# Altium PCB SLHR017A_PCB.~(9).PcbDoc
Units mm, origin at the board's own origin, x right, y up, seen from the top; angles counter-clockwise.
Board outline 79.38 x 53.34 mm, 2 copper layers (Top Layer, Bottom Layer), stack 1.554 mm thick; 50 components, 16 nets, 75 pads, 30 vias.
Unrouted connection lines stored in the file: 2.
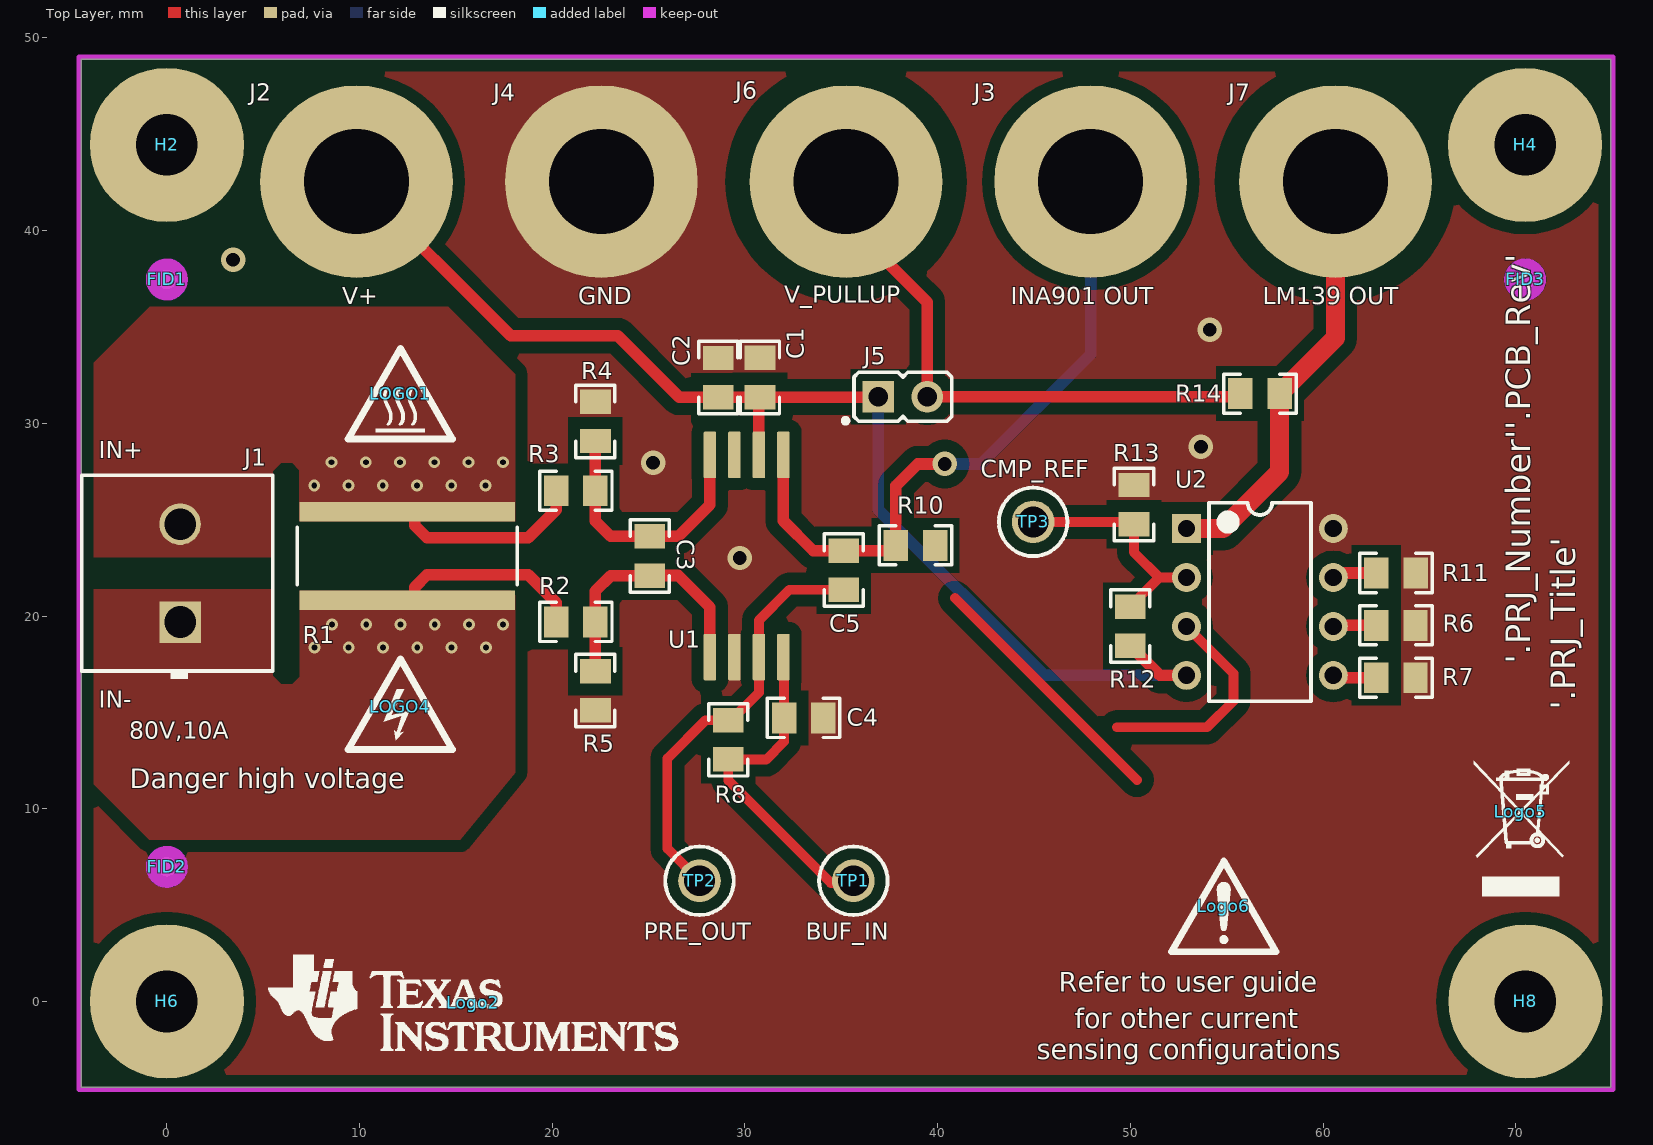
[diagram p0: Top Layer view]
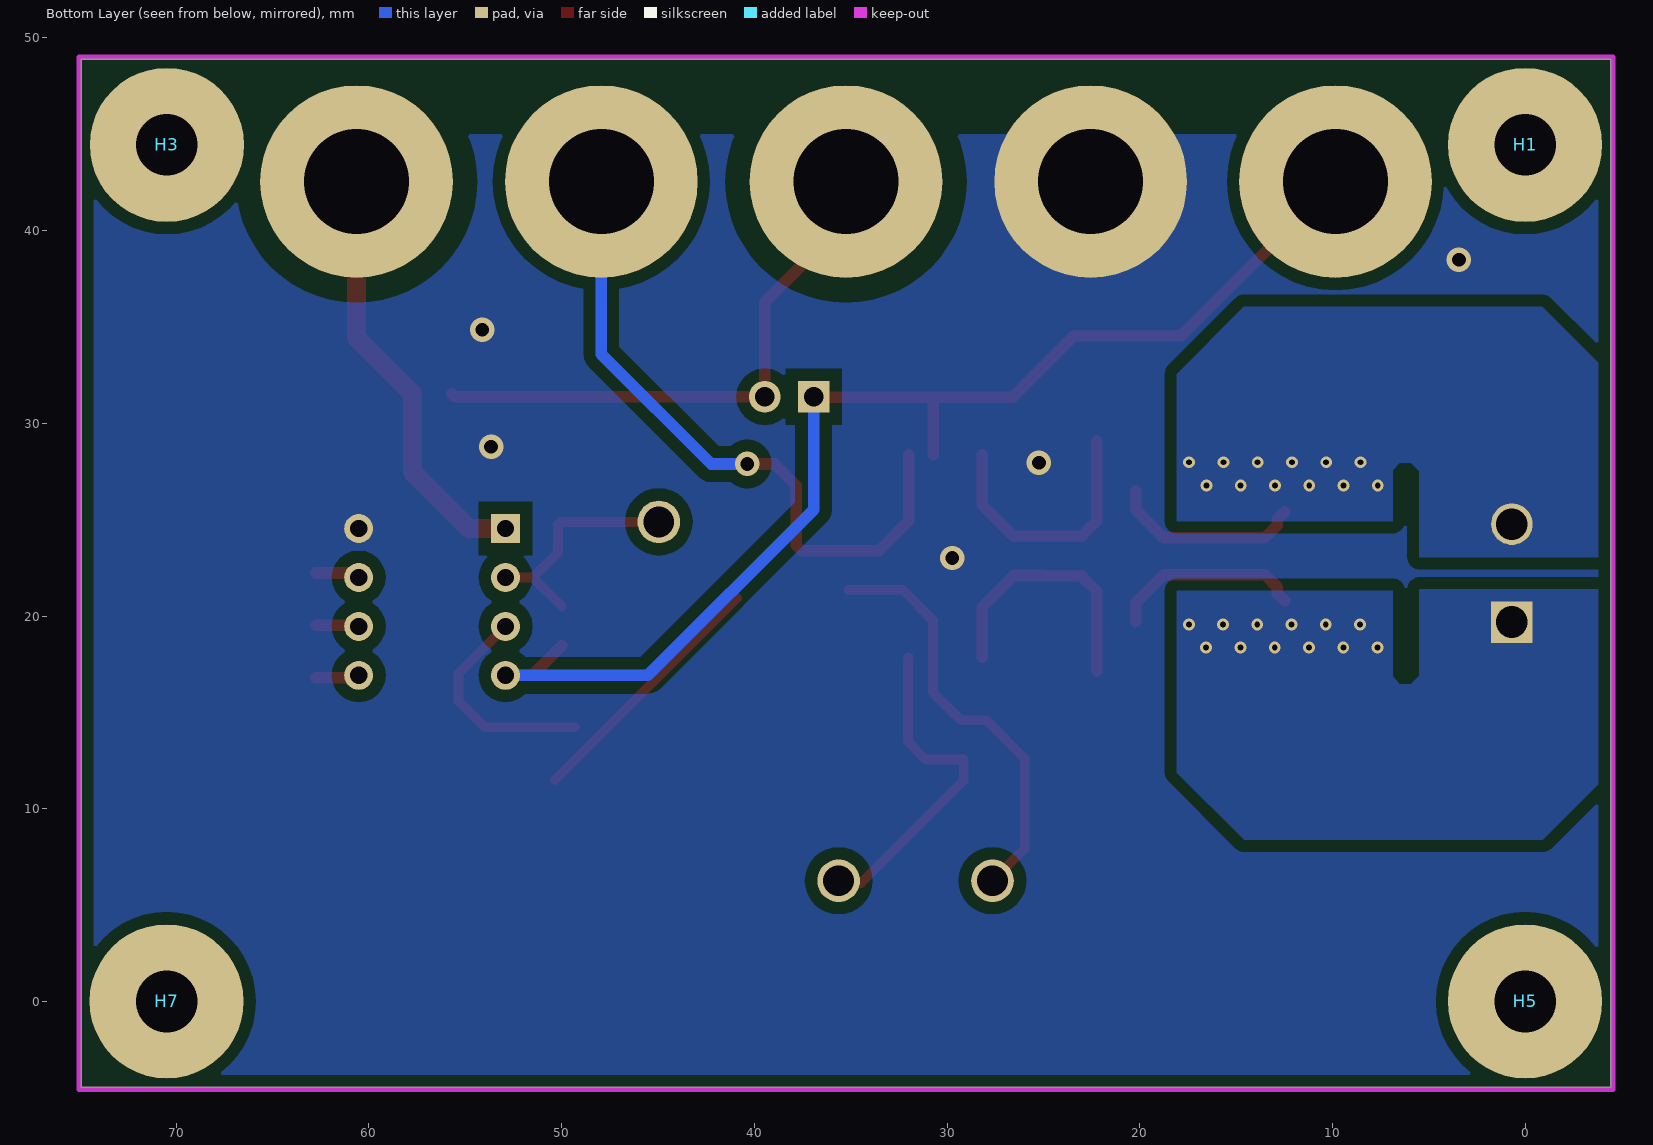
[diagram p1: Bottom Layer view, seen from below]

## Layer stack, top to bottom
Top Solder: solder mask 0.0102, Solder Resist, Dk 3.5
Top Layer: signal copper 0.0533
Dielectric1: core 1.4478, FR-4 High Tg, Dk 4.8
Bottom Layer: signal copper 0.0533
Bottom Solder: solder mask 0.0102, Solder Resist, Dk 3.5

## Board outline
-4.445,-4.445 74.93,-4.445 74.93,48.895 -4.445,48.895
cut-out: -45.497,-56.25 -45.243,-56.25 -45.243,-55.996 -45.497,-55.996

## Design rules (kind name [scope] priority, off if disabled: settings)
AcuteAngle [All] p1: minimum=4.50000000000000E+0001 checktracksonly=FALSE
AssemblyTestPointUsage [All] p1: valid=2
Clearance Clearance_HV [InNetClass('HV_Net')] p1: gap=0.635 ignorepadtopadclearanceinfootprint=TRUE except(1.27: THPad-Poly Poly-Poly)
Clearance Clearance_Keepouts [((IsTrack Or IsArc) And Not InPoly) And IsFree and IsKeepOut vs ((IsTrack Or IsArc) And Not InPoly) And IsFree and IsKeepOut] p2: gap=0 ignorepadtopadclearanceinfootprint=FALSE
Clearance Clearance_Fiducial [InComponentClass('FiducialMark')] p3: gap=0 ignorepadtopadclearanceinfootprint=FALSE
Clearance Clearance_BoardEdge_MountingHoles [OnCopper and InComponentClass('Mounting Holes') vs IsKeepOut] p4: gap=1.016 ignorepadtopadclearanceinfootprint=FALSE except(0.381: Track-THPad)
Clearance Clearance_BoardEdge_Poly [OnCopper and InPoly vs IsKeepOut] p5: gap=0.635 ignorepadtopadclearanceinfootprint=FALSE
Clearance Clearance_Jack_Poly [InPolygon vs InPadClass('Jack')] p6: gap=0.635 ignorepadtopadclearanceinfootprint=FALSE except(1.27: Arc-Poly Track-Poly SMDPad-Poly THPad-Poly Via-Poly Fill-Poly Poly-Poly)
Clearance Clearance_Poly [InPolygon] p7: gap=0.635 ignorepadtopadclearanceinfootprint=FALSE
Clearance [All] p8: gap=0.381 ignorepadtopadclearanceinfootprint=FALSE
ComponentClearance ComponentClearance_MountingHoles_FiducialMarks [InComponentClass('Mounting Holes') vs InComponentClass('FiducialMark')] p1: gap=1.27 collisioncheckmode=3 verticalgap=0.254 showdistances=FALSE
ComponentClearance ComponentClearance_Logo [InComponentClass('Logo')] p2: gap=1.27 collisioncheckmode=3 verticalgap=2540 showdistances=FALSE
ComponentClearance ComponentClearance_ScrewToNut [(HasFootprint('NY PMS 440 0025 PH')) vs (HasFootprint('Keystone_1902C'))] p3: gap=0 collisioncheckmode=3 verticalgap=0 showdistances=FALSE
ComponentClearance ComponentClearance_MountingHoles [InComponentClass('Mounting Holes')] p4: gap=0.762 collisioncheckmode=3 verticalgap=2540 showdistances=FALSE
ComponentClearance [All] p5: gap=0.508 collisioncheckmode=3 verticalgap=0.254 showdistances=FALSE
DiffPairsRouting [All] p1: maxlimit=2.54 minlimit=0.254 mostfreqgap=0.254 toplayer_minwidth=0.381 toplayer_maxwidth=0.381 toplayer_prefwidth=0.381 bottomlayer_minwidth=0.381 bottomlayer_maxwidth=0.381 bottomlayer_prefwidth=0.381 maxuncoupledlength=25.4
FabricationTestPointUsage TestPointUsage [All] p1: valid=2 allowmultiple=FALSE
FabricationTestpoint Testpoint [All] p1: side=3 testpointundercomponent=TRUE minsize=1.016 maxsize=2.54 preferedsize=1.524 minholesize=0 maxholesize=1.016 preferedholesize=0.813 testpointgrid=0.025 allowsidetop=TRUE allowsidebottom=TRUE usegrid=TRUE gridtolerance=0
FanoutControl Fanout_LCC [IsLCC] p1: bgadir=Out bgaviamode=Centered fanoutstyle=Auto fanoutdirection=Alternating viagrid=0.025 // Fanout_LCC (Default Rule)
FanoutControl Fanout_BGA [IsBGA] p2: bgadir=Out bgaviamode=Centered fanoutstyle=Auto fanoutdirection=Alternating viagrid=0.025 // Fanout_BGA (Default Rule)
FanoutControl Fanout_Default [All] p4: bgadir=Out bgaviamode=Centered fanoutstyle=Auto fanoutdirection=Alternating viagrid=0.025 // Fanout_Default (Default Rule)
FanoutControl Fanout_Small [(CompPinCount < 5)] p5: bgadir=Out bgaviamode=Centered fanoutstyle=Auto fanoutdirection=OutThenIn viagrid=0.025 // Fanout_Small (Default Rule)
HoleSize [All] p1: absolutevalues=TRUE maxlimit=6.375 minlimit=0.203 maxpercent=80.000 minpercent=20.000
MinimumAnnularRing [All] p1: minimumring=0.152
MinimumSolderMaskSliver MinimumSolderMaskSliver_Logo [InComponentClass('Logo') vs InComponentClass('Logo')] p1: minsoldermaskwidth=0.018
MinimumSolderMaskSliver [All] p2: minsoldermaskwidth=0.102
PlaneConnect [All] p1: planeconnectstyle=Relief reliefexpansion=0.254 reliefentries=4 reliefconductorwidth=0.254 reliefairgap=0.254
PolygonConnect [All] p1: connectstyle=Direct reliefconductorwidth=0.762 reliefentries=4 polygonreliefangle="90 Angle" airgapwidth=0.381
RoutingVias [All] p1: holewidth=0.305 width=0.61 viastyle="Through Hole" minholewidth=0.305 minwidth=0.61 maxholewidth=0.305 maxwidth=0.61
SilkToBoardRegionClearance [Not ((IsComment or IsDesignator) And (Hide <> 'False')) and not InRegion(1000,500,4000,800)] p1:
SilkToSilkClearance SilkToSilkClearance_Pb-FreeLogo [(HasFootprint('Pb-Free_Overlay_Medium') OR HasFootprint('Pb-Free_Overlay_Small')) vs (HasFootprint('Pb-Free_Overlay_Medium') OR HasFootprint('Pb-Free_Overlay_Small'))] p1: silktosilkclearance=0
SilkToSilkClearance [All] p2: silktosilkclearance=0.102
SilkToSolderMaskClearance SilkToComonentPadClearance [IsPad and InAnycomponent] p1: minsilkscreentomaskgap=0.127 clearancetoexposedcopper=TRUE
SilkToSolderMaskClearance "Silk to Solder Mask Opening" [All] p2: minsilkscreentomaskgap=0.102 clearancetoexposedcopper=FALSE
SolderMaskExpansion [All] p1: expansion=0
Width [All] p1: maxlimit=2.54 minlimit=0.152 preferedwidth=0.254 checkconnectedcopper=TRUE
15 further rules are at their usual default settings.

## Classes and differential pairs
component class Header: J5
component class SLHR017A_MainSheet: C1 C2 C3 C4 C5 J1 J2 J3 J4 J5 J6 J7 R1 R2 R3 R4 R5 R6 R7 R8 R10 R11 R12 R13 R14 TP1 TP2 TP3 U1 U2 U4
component class AssemblyNote: ZZ1 ZZ2 ZZ3
component class FiducialMark: FID1 FID2 FID3
component class SLHR017A_Hardware: FID1 FID2 FID3 H1 H2 H3 H4 H5 H6 H7 H8 LOGO1 Logo2 Logo3 LOGO4 Logo5 Logo6 Logo7 ZZ1 ZZ2 ZZ3
component class Logo: Logo2
component class "Mounting Holes": H2 H4 H6 H8
pad class Jack: J4-1 J6-1 J7-1 J8-1

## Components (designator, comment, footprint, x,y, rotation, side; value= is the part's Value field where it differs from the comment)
C1 "C0805C104K1RACTU" 0805_HV 30.776,32.379 r90 top value=0.1uF
C2 "C0805C103F1GACTU" 0805_HV 28.612,32.375 r90 top value=0.01uF
C3 "C0805C101J1RACTU" 0805_HV 25.062,23.114 r270 top value=100pF
C4 "C0805C103F1GACTU" 0805_HV 33.045,14.714 r0 top value=0.01uF
C5 "C0805C103F1GACTU" 0805_HV 35.127,22.382 r90 top value=0.01uF
FID1 "Fiducial" Fiducial10-20 0,37.465 r270 top locked
FID2 "Fiducial" Fiducial10-20 0,6.985 r0 top locked
FID3 "Fiducial" Fiducial10-20 70.485,37.465 r180 top locked
H1 "1902C" Keystone_1902C 0,44.45 r180 bottom locked
H2 "NY PMS 440 0025 PH" "NY PMS 440 0025 PH" 0,44.45 r0 top locked
H3 "1902C" Keystone_1902C 70.485,44.45 r180 bottom locked
H4 "NY PMS 440 0025 PH" "NY PMS 440 0025 PH" 70.485,44.45 r0 top locked
H5 "1902C" Keystone_1902C 0,0 r180 bottom locked
H6 "NY PMS 440 0025 PH" "NY PMS 440 0025 PH" 0,0 r0 top locked
H7 "1902C" Keystone_1902C 70.498,0 r180 bottom locked
H8 "NY PMS 440 0025 PH" "NY PMS 440 0025 PH" 70.498,0 r0 top locked
J1 "039544-3002" Molex_039544-3002 0.69,22.225 r90 top
J2 "V+" Keystone_575-4 9.842,42.545 r0 top
J3 "INA_OUT" Keystone_575-4 47.942,42.545 r0 top
J4 "GND" Keystone_575-4 22.542,42.545 r0 top
J5 "PBC02SAAN" Sullins_PBC02SAAN 38.191,31.38 r90 top
J6 "VPULLUP" Keystone_575-4 35.242,42.545 r0 top
J7 "COMP_OUT" Keystone_575-4 60.642,42.545 r0 top
LOGO1 "CAUTION HOT SURFACE" IEC_HotSurface_Small 12.115,31.542 r0 top
Logo2 "Texas Instruments" TI_Stacked_Overlay_Small 15.897,-0.073 r0 top
Logo3 "FCC disclaimer" FCC_disclaimer 49.467,-37.52 r270 top locked
LOGO4 "DANGER HIGH VOLTAGE" IEC_HighVoltage_Small 12.116,15.3 r0 top
Logo5 "WEEE logo" WEEE_Minimum 70.251,9.843 r0 top
Logo6 "CAUTION.  READ USER GUIDE BEFORE USE" IEC_Caution_Small 54.848,4.937 r0 top
R1 "KRL11050-C-R050-F-T1" 4320 12.471,23.114 r90 top value=0.05
R2 "ERJ-6GEY0R00V" 0805_HV 21.218,19.693 r0 top value=0
R3 "ERJ-6GEY0R00V" 0805_HV 21.218,26.505 r0 top value=0
R4 "ERJ-6GEY0R00V" 0805_HV 22.234,30.099 r90 top value=0
R5 "ERJ-6GEY0R00V" 0805_HV 22.234,16.129 r90 top value=0
R6 "CRCW080510M0FKEA" 0805_HV 63.782,19.515 r180 top value=10.0Meg
R7 "RNCP0805FTD10K0" 0805_HV 63.782,16.797 r180 top value=10.0k
R8 "ERJ-6GEY0R00V" 0805_HV 29.135,13.577 r90 top value=0
R10 "ERJ-6GEY0R00V" 0805_HV 38.851,23.668 r0 top value=0
R11 "RNCP0805FTD10K0" 0805_HV 63.782,22.233 r0 top value=10.0k
R12 "ERJ-6GEYJ153V" 0805_HV 49.991,19.476 r270 top value=15k
R13 "ERJ-6GEYJ153V" 0805_HV 50.191,25.785 r270 top value=15k
R14 "ERJ-6GEYJ302V" 0805_HV 56.726,31.541 r180 top value=3.0k
TP1 "BUF_IN" Keystone5010 35.624,6.262 r90 top
TP2 "PRE_OUT" Keystone5010 27.64,6.262 r90 top
TP3 "CMP_REF" Keystone5010 44.956,24.887 r90 top
U1 "INA901HKX/EM" HKX0008A_Custom_B 30.088,23.116 r90 top
U2 "LM193AJRLQMLV" NAB0008A 56.722,20.73 r0 top
ZZ1 "These assemblies are ESD sensitive, ESD precautions shall be observed." AssemblyNote 112.471,32.481 r0 top
ZZ2 "These assemblies must be clean and free from flux and all contaminants. Use of no clean flux is not acceptable." AssemblyNote 112.471,30.232 r0 top
ZZ3 "These assemblies must comply with workmanship standards IPC-A-610 Class 2, unless otherwise specified." AssemblyNote 112.471,27.983 r0 top

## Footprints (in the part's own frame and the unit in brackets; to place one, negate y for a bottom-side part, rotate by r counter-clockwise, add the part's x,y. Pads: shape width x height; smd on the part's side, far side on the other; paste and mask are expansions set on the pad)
0805_HV [mil] "0805 with 30mil clearance between pads"
  rect 50x63 smd: 1(-40,0) 2(40,0)
  silkscreen extent -74,-40 74,40, body extent -43,-29 43,29, height 57
4320 [mm] "SUSUMU"
  rect 1x11.2 smd: 1(-2.3,0) 2(2.3,0)
  silkscreen extent -1.5,-5.7 1.5,5.7, body extent -2.6,-5.6 2.6,5.6, height 0.7
AssemblyNote [mm] "Assembly Note"
FCC_disclaimer [mm]
Fiducial10-20 [mm]
  round 1 smd mask+0.5: 1(0,0)
  Top Layer keep-out circle w1.178: c0,0 r0.5
HKX0008A_Custom_B [mm] "CFP, 8-Leads, Body 6.73x6.74mm (max), Pitch 1.27mm, IPC Medium Density"
  rrect15% 2.4x0.65 smd: 1(-5.25,1.905) 2(-5.25,0.635) 3(-5.25,-0.635) 4(-5.25,-1.905) 5(5.25,-1.905) 6(5.25,-0.635) 7(5.25,0.635) 8(5.25,1.905)
  body extent -3.25,-3.24 3.25,3.24, height 2.51
IEC_Caution_Small [mm]
  silkscreen extent -2.72,-2.36 2.72,2.35
IEC_HighVoltage_Small [mm]
  silkscreen extent -2.72,-2.24 2.72,2.47
IEC_HotSurface_Small [mm]
  silkscreen extent -2.72,-2.36 2.72,2.35
Keystone5010 [mil] "Keystone Multipurpose loops"
  round 87 hole 63: 1(0,0)
  silkscreen extent -70,-70 70,70, body extent -63,-63 63,62, height 319
Keystone_575-4 [mm] "Banana Jack"
  round 10 hole 5.45: 1(0,0)
  body extent -3.95,-3.95 3.92,3.93, height 2.36
Keystone_1902C [mil] "Hex Standoff, 4-40 threaded, nylon"
  round 1 on Mech4: 0(0,0)
  body extent -145,-126 146,126, height 501
Molex_039544-3002 [mm] "Terminal Block, 5.08mm, 2x1, TH"
  rect 2.15x2.15 hole 1.65: 1(-2.54,0)
  round 2.15 hole 1.65: 2(2.54,0)
  silkscreen extent -5.5,-4.8 5.08,5.11, body extent -5.08,-4.8 5.08,5.11, height 14.48
NAB0008A [mm] "DIP, 8-Leads, Row Spacing 7.62mm, Pitch 2.54mm, Body 9.78x6.73mm"
  rect 1.5x1.5 hole 0.9: 1(-3.81,3.81)
  round 1.5 hole 0.9: 2(-3.81,1.27) 3(-3.81,-1.27) 4(-3.81,-3.81) 5(3.81,-3.81) 6(3.81,-1.27) 7(3.81,1.27) 8(3.81,3.81)
  silkscreen extent -2.65,-5.15 2.65,5.15, body extent -3.91,-5.08 3.96,5.08, height 5.17
"NY PMS 440 0025 PH" [mm] "4-40 nylon screw and mounting hole"
  round 8 hole 3.2: 1(0,0)
  body extent -3.3,-3.3 3.3,3.3, height 2.69
Sullins_PBC02SAAN [mm] "Sullins 100mil, 1x2, 230 mil above insulator"
  rect 1.65x1.65 hole 1.016: 1(0,1.27)
  round 1.65 hole 1.016: 2(0,-1.27)
  silkscreen extent -1.37,-2.54 1.27,3.1, body extent -1.27,-2.54 1.27,2.54, height 8.38
TI_Stacked_Overlay_Small [mm]
  silkscreen extent -10.63,-2.49 10.63,2.49
WEEE_Minimum [mm] "WEEElie bin"
  silkscreen extent -2.42,-4.38 2.52,2.65

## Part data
C1: library part CMP-0007722-2, "CAP, CERM, 0.1 uF, 100 V, +/- 10%, X7R, 0805", Cap_Case=0805, Manufacturer=Kemet, Supplier Part Number 1=399-3486-1-ND, TempCo=X7R, Tolerance_%=10%, Value1="0.064 ohm", Value2=100V, ValueDisplayed=0.1uF
C2 C4 C5: library part CMP-0007716-2, "CAP, CERM, 0.01 uF, 100 V, +/- 1%, C0G/NP0, 0805", Cap_Case=0805, Manufacturer=Kemet, Supplier Part Number 1=399-11160-1-ND, TempCo=C0G/NP0, Tolerance_%=1%, Value1=Unknown, Value2=100V, ValueDisplayed=0.01uF
C3: library part CMP-0007706-2, "CAP, CERM, 100 pF, 100 V, +/- 5%, X7R, 0805", Cap_Case=0805, Manufacturer=Kemet, Supplier Part Number 1=80-C0805C101J1R, TempCo=X7R, Tolerance_%=5%, Value1=Unknown, Value2=100V, ValueDisplayed=100pF
FID1 FID2 FID3: library part CMP-0077181-1, "Fiducial mark.  There is nothing to buy or mount.", Manufacturer=N/A
H1 H3 H5 H7: library part CMP-0003610-1, "Standoff, Hex, 0.5\"L #4-40 Nylon", Manufacturer=Keystone, Supplier Part Number 1=36-1902C-ND
H2 H4 H6 H8: library part CMP-0003617-1, "Machine Screw, Round, #4-40 x 1/4, Nylon, Philips panhead", Manufacturer="B&F Fastener Supply", Supplier Part Number 1=H542-ND
J1: library part CMP-0055345-1, "Terminal Block, 5.08mm, 2x1, TH", Color=Black, Current_A=15A, Manufacturer=Molex, Supplier Part Number 1=WM7853-ND, Voltage_V=300V
J2 J3 J4 J6 J7: library part CMP-0055165-2, "Standard Banana Jack, Uninsulated, 5.5mm", Manufacturer=Keystone, PartNumber=575-4, Supplier Part Number 1=36-575-4-ND
J5: library part CMP-0054566-1, "Header, 100mil, 2x1, Gold, TH", Color=Black, Current_A=3A, Manufacturer="Sullins Connector Solutions", Supplier Part Number 1=S1011E-02-ND, Voltage_V=1.8kV
LOGO1: library part CMP-0074837-1, "IEC 61010-1 Hot Surface Warning"
Logo2: library part CMP-0074838-1, "Texas Instrument Corporate Signature"
Logo3: library part CMP-0074847-1, "FCC_disclaimer"
LOGO4: library part CMP-0074835-1, "IEC 61010-1 High Voltage Warning"
Logo5: library part CMP-0074769-1
Logo6: library part CMP-0074836-1, "IEC 61010-1 Caution Warning"
R1: library part CMP-0015099-2, "RES, 0.05, 1%, 6 W, 4320_WIDE", Manufacturer="Susumu Co Ltd", Power_W=6W, Supplier Part Number 1=KRL11C.050CT-ND, TempCo="50 ppm/C", Tolerance_%=1%, Value_Code=R050, ValueDisplayed=0.05
R2 R3 R4 R5 R8 R10: library part CMP-0020616-3, "RES, 0, 5%, 0.125 W, AEC-Q200 Grade 0, 0805", Manufacturer=Panasonic, Power_W=125mW, Supplier Part Number 1=P0.0ACT-ND, TempCo="600 ppm/C", Tolerance_%=5%, Value2=0.125W, Value_Code=0000, ValueDisplayed=0
R6: library part CMP-0020846-3, "RES, 10.0 M, 1%, 0.125 W, AEC-Q200 Grade 0, 0805", Manufacturer=Vishay-Dale, Power_W=125mW, Supplier Part Number 1=541-10.0MCCT-ND, TempCo="100 ppm/C", Tolerance_%=1%, Value2=0.125W, Value_Code=10M0, ValueDisplayed=10.0M
R7 R11: library part CMP-0084247-1, "RES, 10.0 k, 1%, 0.25 W, AEC-Q200 Grade 0, 0805", Manufacturer="Stackpole Electronics Inc", Power_W=250mW, TempCo="100 ppm/C", Tolerance_%=1%, Value2=0.25W, Value_Code=10k0, ValueDisplayed=10.0k
R12 R13: library part CMP-0020646-3, "RES, 15 k, 5%, 0.125 W, AEC-Q200 Grade 0, 0805", Manufacturer=Panasonic, Power_W=125mW, Supplier Part Number 1=P15KACT-ND, TempCo="200 ppm/C", Tolerance_%=5%, Value2=0.125W, Value_Code=15k0, ValueDisplayed=15k
R14: library part CMP-0020698-3, "RES, 3.0 k, 5%, 0.125 W, AEC-Q200 Grade 0, 0805", Manufacturer=Panasonic, Power_W=125mW, Supplier Part Number 1=P3.0KACT-ND, TempCo="200 ppm/C", Tolerance_%=5%, Value2=0.125W, Value_Code=3k00, ValueDisplayed=3.0k
TP1 TP2 TP3: library part CMP-0055147-1, "Test Point, Multipurpose, Red, TH", Color=Red, Manufacturer=Keystone, PartNumber=5010, Supplier Part Number 1=36-5010-ND
U1: library part CMP-0081563-2, "Voltage Output, Unidirectional Measurement Current-Shunt Monitor, HKX0008A (CFP-8)", Alternate Manufacturer="Texas Instruments", Rating=Space
U2: library part CMP-0067897-1, "Low Power Low Offset Voltage Dual Comparator, 8-pin CerDIP", Manufacturer="Texas Instruments", Package Reference=NAB0008A, PackageTopMarking="NSZSSXXYYA*LM193AJRLV Q*5962R*9452603VPA", PowerWise=N
ZZ1: library part CMP-0077236-1
ZZ2: library part CMP-0077237-1
ZZ3: library part CMP-0077238-1

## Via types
v1: diameter 0.61, hole 0.305, Top Layer to Bottom Layer, tented both sides, 24 vias
v2: diameter 1.27, hole 0.711, Top Layer to Bottom Layer, 6 vias

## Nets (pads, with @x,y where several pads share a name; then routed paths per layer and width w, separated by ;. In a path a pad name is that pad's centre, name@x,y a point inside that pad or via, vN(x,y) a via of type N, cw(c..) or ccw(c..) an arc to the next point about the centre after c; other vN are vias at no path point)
GND: C1.2 C2.2 C4.2 J4.1 R4.2 R5.1 R6.1 R7.1 R11.2 R13.1 U1.2 U2.8
  other v2: 29.733,23.012 25.228,27.961 53.663,28.785 54.117,34.857 3.433,38.489
NetC3_1: C3.1 R3.2 R4.1 U1.8 | length 13.7
  Top Layer w0.6: R4.1 R3.2 22.234,24.933 23.037,24.13 C3.1 26.542,24.13 28.183,25.77 U1.8
NetC3_2: C3.2 R2.2 R5.2 U1.1 | length 13.7
  Top Layer w0.6: R5.2 R2.2 22.234,21.295 23.037,22.098 C3.2 ; C3.2@25.062,22.102 26.542,22.102 28.183,20.462 U1.1
NetC4_1: C4.1 R8.1 TP1.1 U1.4 | length 17.5
  Top Layer w0.508: U1.4 32.029,17.83 C4.1 32.029,13.484 31.106,12.561 R8.1 29.135,11.47 34.456,6.149 TP1.1@35.624,6.149
NetC5_1: C5.1 R8.2 TP2.1 U1.3 | length 22
  Top Layer w0.508: TP2.1 25.97,7.932 25.97,12.608 27.956,14.593 R8.2 29.279,14.593 30.723,16.037 U1.3 30.723,19.783 32.306,21.366 C5.1
NetC5_2: C5.2 J3.1 R10.1 U1.5 | length 35
  Top Layer w0.6: U1.5 31.993,24.938 33.533,23.398 C5.2 37.565,23.398 R10.1 37.835,26.76 38.967,27.891 v2(40.371,27.891)
  Bottom Layer w0.6: v2(40.371,27.891) 42.24,27.891 47.942,33.594 J3.1
NetJ1_1: J1.1 R1.1 R2.1 | length 10.1
  Top Layer w0.6: R1.1@12.471,20.785 12.86,21.174 12.86,21.501 13.499,22.14 18.745,22.14 20.202,20.682 R2.1
  other v1: 7.655,18.364 9.433,18.364 11.211,18.364 12.989,18.364 14.767,18.364 16.557,18.364 8.565,19.558 10.343,19.558 12.121,19.558 13.899,19.558 15.671,19.558 17.444,19.558
NetJ1_2: J1.2 R1.2 R3.1 | length 10.1
  Top Layer w0.6: R1.2 12.86,25.025 12.86,24.698 13.499,24.059 18.745,24.059 20.202,25.516 R3.1
  other v1: 7.648,26.775 9.426,26.775 11.204,26.775 12.982,26.775 14.76,26.775 16.538,26.775 8.546,27.983 10.324,27.983 12.102,27.983 13.88,27.983 15.658,27.983 17.436,27.983
NetJ5_2: J5.2 J6.1 R14.2 | length 29.2
  Top Layer w0.6: J6.1 35.242,40.506 39.461,36.287 J5.2 55.549,31.38 R14.2
NetJ7_1: J7.1 R14.1 U2.1 | length 22.3
  Top Layer w1: U2.1 54.802,24.54 57.742,27.48 R14.1 60.642,34.441 J7.1
NetR6_2: R6.2 U2.6 | length 2.3
  Top Layer w0.6: U2.6 60.587,19.515 R6.2
NetR7_2: R7.2 U2.5 | length 2.3
  Top Layer w0.6: U2.5 60.656,16.797 R7.2
NetR10_2: R10.2 U2.3 | length 24.8
  Top Layer w0.508: 40.905,20.935 50.345,11.496 ; 49.307,14.229 53.98,14.229 55.349,15.598 55.349,17.024 U2.3
NetR11_1: R11.1 U2.7 | length 2.3
  Top Layer w0.6: U2.7 60.765,22.233 R11.1
NetR12_1: R12.1 R13.2 TP3.1 U2.2 | length 12.1
  Top Layer w0.508: TP3.1 50.072,24.887 R13.2 50.191,23.308 51.499,22 ; R12.1 51.499,22 ; U2.2 51.499,22
V+: C1.1 C2.1 J2.1 J5.1 R12.2 U1.6 U2.4 | length 63.7
  Top Layer w0.6: J2.1 17.843,34.544 23.399,34.544 26.584,31.359 C2.1 28.617,31.363 C1.1 ; U1.6 30.723,31.31 C1.1 ; J5.1@36.887,31.552 36.699,31.363 C1.1 ; R12.2 51.531,16.92 U2.4
  Bottom Layer w0.6: J5.1 36.921,25.522 45.523,16.92 U2.4
pads on no net: FID1.1 FID2.1 FID3.1 H1.0 H2.1 H3.0 H4.1 H5.0 H6.1 H7.0 H8.1 U1.7

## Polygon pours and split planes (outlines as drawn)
NetJ1_1 on Bottom Layer "NETJ1_1_L02_P278" (solid, remove dead copper, pour order 278): 18.071,21.311 18.071,11.876 14.686,8.49 14.585,8.383 -0.914,8.383 -4.406,11.876 -4.406,21.383 5.469,21.383 5.49,21.404 5.49,16.907 5.934,16.463 6.505,16.463 6.861,16.865 6.861,21.311
NetJ1_2 on Bottom Layer "NETJ1_2_L02_P280" (solid, remove dead copper, pour order 280): 18.071,24.914 18.082,32.554 14.697,35.939 14.596,36.046 -0.903,36.046 -4.395,32.554 -4.395,23.046 5.48,23.046 5.501,23.025 5.501,27.522 5.944,27.966 6.516,27.966 6.872,27.565 6.872,24.918
GND on Bottom Layer "GND" (solid, remove dead copper, pour order 282): -4.761,-8.326 74.61,-8.326 74.61,45.014 74.61,45.015 -4.76,45.015 -4.763,45.012
NetJ1_2 on Top Layer "NETJ1_2_L01_P272" (solid, remove dead copper, pour order 272): 18.071,24.914 18.082,32.554 14.697,35.939 14.596,36.046 -0.903,36.046 -4.395,32.554 -4.395,23.046 5.48,23.046 5.501,23.025 5.501,27.522 5.944,27.966 6.516,27.966 6.872,27.565 6.872,24.918
no net on Top Layer "NONET_L01_P288" (solid, remove dead copper, pour order 288): 18.076,11.338
NetJ1_1 on Top Layer "NETJ1_1_L01_P274" (solid, remove dead copper, pour order 274): 18.071,21.286 18.087,21.27 18.071,11.876 15.188,8.342 15.147,8.383 -0.914,8.383 -4.406,11.876 -4.406,21.383 5.469,21.383 5.49,21.404 5.49,16.907 5.934,16.463 6.505,16.463 6.898,16.856 6.898,21.311 18.024,21.311 18.035,21.299
GND on Top Layer "GND_L01_P286" (solid, remove dead copper, pour order 286): -4.556,49.057 -4.554,49.055 74.816,49.055 74.816,-4.285 -4.559,-4.285

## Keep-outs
Keep-Out Layer:
  lines w0.254: -4.572,-4.572 75.057,-4.572 75.057,49.022 -4.572,49.022 -4.572,-4.572
  text ".Layer_Name" at -13.265,-39.092 h1.52

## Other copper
Top Layer:
  text ".Layer_Name" at -13.265,-39.092 h1.52
Bottom Layer:
  text ".Layer_Name" at -13.265,-39.092 h1.52

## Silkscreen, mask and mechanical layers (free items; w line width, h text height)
Top Overlay:
  text "V_PULLUP" at 32.038,36.262 h0.89
  text "V+" at 9.102,36.188 h0.89
  text "GND" at 21.358,36.188 h0.89
  text "INA901 OUT" at 43.795,36.188 h0.89
  text "LM139 OUT" at 56.865,36.188 h0.89
  text "IN+" at -3.549,28.193 h0.89
  text "'.PRJ_Number''.PCB_Rev'" at 70.744,17.524 h1.27 r90
  text "IN-" at -3.549,15.24 h0.89
  text "'.PRJ_Title'" at 73.087,15.128 h1.27 r90
  text "80V,10A" at -1.956,13.639 h0.89
  text "Danger high voltage" at -1.922,11.062 h1.02
  text "Refer to user guide" at 46.292,0.496 h1.02
  text "for other current" at 47.105,-1.396 h1.02
  text "sensing configurations" at 45.131,-3.007 h1.02
  text ".Layer_Name" at -13.265,-39.092 h1.52
Bottom Overlay:
  text ".Layer_Name" at -13.265,-39.092 h1.52
Top Paste:
  text ".Layer_Name" at -13.265,-39.092 h1.52
Bottom Paste:
  text ".Layer_Name" at -13.265,-39.092 h1.52
Top Solder:
  text ".Layer_Name" at -13.265,-39.092 h1.52
  text ".Layer_Name" at -13.265,-39.092 h1.52
Bottom Solder:
  text ".Layer_Name" at -13.265,-39.092 h1.52
Drill Guide:
  text ".Layer_Name" at -13.265,-39.092 h1.52
M1 Board Outline:
  the board outline again, w0.254
  text ".Layer_Name" at -13.265,-39.092 h1.52
M2 Board Dimensions:
  rectangle: -24.745,-27.446 -15.22,-24.271
  rectangle: -27.92,-24.271 -24.745,-21.096
  lines w0.178: -27.92,-24.271 -2.52,-24.271 ; -24.745,-27.446 -24.745,-21.096 ; -21.57,-27.446 -21.57,-21.096 ; -15.22,-27.446 -15.22,-21.096 ; -8.87,-27.446 -8.87,-21.096 ; -27.92,-27.446 -27.92,-21.096 -2.52,-21.096 -2.52,-27.446 -27.92,-27.446
  text ".Layer_Name" at -13.265,-39.092 h1.52
M3 3D STEP Top:
  text ".Layer_Name" at -13.265,-39.092 h1.52
M4 3D STEP Bottom:
  text ".Layer_Name" at -13.265,-39.092 h1.52
M5 Assembly Top:
  lines w0.254: -35.337,-40.913 132.303,-40.913 ; -35.337,-35.748 132.354,-35.748 ; -35.337,-30.583 -35.337,-46.077 66.39,-46.077 132.354,-46.077 132.354,-30.583 -35.325,-30.583 -35.325,-46.077 4.693,-46.077 ; 27.274,-46.077 27.274,-30.583 ; 59.456,-35.748 59.456,-30.583 ; 80.792,-35.748 80.792,-30.583 ; 96.59,-46.242 96.59,-41.09
  text "COMPONENTS MARKED 'DNP' SHOULD NOT BE POPULATED." at 1.378,-25.376 h1.52
  text "ASSEMBLY VARIANT:" at 1.366,-28.31 h1.52
  text ".VariantName" at 27.68,-28.31 h1.52
  text "PCB VIEWED FROM TOP SIDE" at -33.724,-33.94 h1.52
  text "BOARD #:" at 29.179,-33.94 h1.52
  text ".PRJ_Number" at 43.034,-33.94 h1.52
  text "REV:" at 64.485,-33.94 h1.52
  text ".PCB_Rev" at 71.889,-33.94 h1.52
  text "SVN REV:" at 85.77,-33.94 h1.52
  text ".VersionControl_RevNumber" at 98.622,-33.94 h1.52
  text "TID #:" at 29.179,-39.105 h1.52
  text ".TID" at 43.034,-39.105 h1.52
  text "PLOT NAME =" at -33.724,-44.32 h1.52
  text ".plot_File_Name" at -13.265,-44.32 h1.52
  text "GENERATED    :" at 29.23,-44.32 h1.52
  text ".Print_Date" at 51.315,-44.32 h1.52
  text ".Print_Time" at 69.831,-44.32 h1.52
  text "TEXAS INSTRUMENTS" at 101.95,-44.32 h1.52
M6 Assembly Bottom:
  lines w0.254: -35.35,-35.761 132.341,-35.761 ; -35.299,-40.925 132.341,-40.925 ; 0.413,-46.255 0.413,-41.103 ; 16.212,-35.761 16.212,-30.596 ; 37.548,-35.761 37.548,-30.596 ; 69.73,-46.09 69.73,-30.596 ; 92.31,-46.09 132.328,-46.09 132.328,-30.596 -35.35,-30.596 -35.35,-46.09 30.614,-46.09 132.341,-46.09 132.341,-30.596
  text "COMPONENTS MARKED 'DNP' SHOULD NOT BE POPULATED." at 127.07,-25.363 h1.52
  text ".VariantName" at 100.553,-28.31 h1.52
  text "ASSEMBLY VARIANT:" at 126.943,-28.31 h1.52
  text ".VersionControl_RevNumber" at -1.619,-33.953 h1.52
  text "SVN REV:" at 11.234,-33.953 h1.52
  text ".PCB_Rev" at 25.115,-33.953 h1.52
  text "REV:" at 32.519,-33.953 h1.52
  text ".PRJ_Number" at 53.969,-33.953 h1.52
  text "BOARD #:" at 67.825,-33.953 h1.52
  text "PCB VIEWED FROM BOTTOM SIDE" at 130.728,-33.953 h1.52
  text ".TID" at 53.969,-39.118 h1.52
  text "TID #:" at 67.825,-39.118 h1.52
  text "TEXAS INSTRUMENTS" at -4.946,-44.333 h1.52
  text ".Print_Time" at 27.172,-44.333 h1.52
  text ".Print_Date" at 45.689,-44.333 h1.52
  text "GENERATED    :" at 67.774,-44.333 h1.52
  text ".plot_File_Name" at 110.268,-44.333 h1.52
  text "PLOT NAME =" at 130.728,-44.333 h1.52
M7 LPKF Text Top:
  text ".Layer_Name" at -13.265,-39.092 h1.52
M8 LPKF Text Bottom:
  text ".Layer_Name" at -13.265,-39.092 h1.52
M9 Title Sheet:
  drawing of 57 lines, arcs and shapes, not listed
  text "1" at -9.129,186.841 h1.78
  text "2" at 54.261,186.841 h1.78
  text "3" at 117.491,186.841 h1.78
  text "4" at 181.16,186.841 h1.78
  text "5" at 244.634,186.841 h1.78
  text "6" at 308.261,186.841 h1.78
  text "A" at -38.5,157.809 h1.78
  text "A" at 337.42,157.809 h1.78
  text "B" at -38.5,97.357 h1.78
  text "B" at 337.42,97.357 h1.78
  text "C" at -38.5,37.032 h1.78
  text "C" at 337.42,37.032 h1.78
  text "PROJECT TITLE:" at 260.204,-10.238 h1.14
  text ".PRJ_Title" at 261.474,-13.624 h1.78
  text "DESIGNED FOR:" at 260.204,-17.883 h1.14
  text ".PRJ_Customer" at 261.474,-21.439 h1.78
  text "D" at -38.5,-23.166 h1.78
  text "D" at 337.42,-23.166 h1.78
  text "FILE NAME:" at 260.204,-25.503 h1.14
  text ".PCB_File_Name_No_Path" at 261.474,-28.551 h1.78
  text "Texas Instruments (TI) and/or its licensors do not warrant the accuracy or completeness of this specification" at 133.979,-32.662 h1.14
  text "ENGINEER:" at 260.204,-32.869 h1.14
  text "LAYOUT BY:" at 298.431,-32.869 h1.14
  text "or any information contained therein. TI and/or its licensors do not warrant that this design will meet" at 132.837,-35.524 h1.14
  text ".PRJ_Engineer" at 261.474,-36.806 h1.78
  text ".PCB_Layout" at 299.714,-36.806 h1.78
  text "the specifications, will be suitable for your application or fit for any particular purpose, or will operate in" at 132.837,-38.385 h1.14
  text ".Layer_Name" at -13.265,-39.092 h1.52
  text "ALTIUM DESIGNER VERSION:" at 298.431,-40.743 h1.14
  text "an implementation. TI and/or its licensors do not warrant that the design is production worthy. You should" at 132.837,-41.247 h1.14
  text "completely validate and test your design implementation to confirm the system functionality for your application." at 133.979,-44.109 h1.14
  text ".print_Scale" at 261.474,-44.13 h1.78
  text ".Application_BuildNumber" at 299.714,-44.13 h1.78
  text "1" at -9.129,-49.379 h1.78
  text "2" at 54.261,-49.379 h1.78
  text "3" at 117.491,-49.379 h1.78
  text "4" at 181.16,-49.379 h1.78
  text "5" at 244.634,-49.379 h1.78
  text "6" at 291.82,-49.527 h1.78
  text "WO#307451-7449-D" at 301.978,-49.59 h1.78
M10 Fab Notes:
  drawing of 189 lines, arcs and shapes, not listed
  text "DESIGN INFORMATION" at 286.926,144.161 h1.52
  text "20" at 297.351,140.825 h1.52
  text "MIN. TRACK WIDTH:" at 270.554,140.805 h1.52
  text "MIL" at 302.329,140.805 h1.52
  text "MIN. CLEARANCE:" at 270.554,137.652 h1.52
  text "MIL" at 302.329,137.652 h1.52
  text "19.7" at 296.193,137.59 h1.52
  text "24" at 296.867,134.714 h1.52
  text "MIN. VIA PAD SIZE:" at 270.554,134.499 h1.52
  text "MIL" at 302.329,134.499 h1.52
  text "0.05mm (2MIL)" at 288.207,131.199 h1.52
  text "MINIMUM ANNULAR RING" at 262.191,130.991 h1.52
  text "EXTERNAL" at 306.19,130.991 h1.52
  text "PER" at 267.271,128.193 h1.52
  text "IPC-D-275 CLASS 2 LEVEL C" at 272.859,128.193 h1.52
  text "MIL, HOLES" at 310.661,125.641 h1.52
  text "+/-" at 300.692,125.423 h1.52
  text "+/-" at 322.384,125.423 h1.52
  text "REGISTRATION TOLERANCES:" at 262.191,125.396 h1.52
  text "METAL" at 292.666,125.396 h1.52
  text "5" at 307.301,125.396 h1.52
  text "3" at 328.459,125.396 h1.52
  text "MIL" at 331.412,125.396 h1.52
  text "HOLE SIZE TOLERANCE (UNLESS OTHERWISE SPECIFIED):" at 262.191,122.899 h1.52
  text "+/-" at 322.384,122.826 h1.52
  text "3" at 328.459,122.799 h1.52
  text "MIL" at 331.412,122.799 h1.52
  text "MATERIAL:" at 260.292,119.303 h1.52
  text "FR-4 High Tg" at 285.348,116.038 h1.52
  text "FR-408" at 270.986,115.721 h1.52
  text "OTHER" at 308.781,115.721 h1.52
  text "X" at 281.581,115.683 h1.52
  text "62 MIL (1.6mm) +/-10%" at 279.116,112.088 h1.52
  text "X" at 276.066,112.025 h1.52
  text "THICKNESS:" at 262.191,111.879 h1.52
  text "OTHER" at 311.753,111.879 h1.52
  text "TOLERANCE:" at 262.191,108.366 h1.52
  text "X" at 283.737,108.366 h1.52
  text "ANSI IPC-6012 TYPE 3 CLASS 2" at 288.258,108.366 h1.52
  text "OTHER +/-" at 288.258,104.703 h1.52
  text "BOW & TWIST:" at 262.191,101.015 h1.52
  text "X" at 283.737,101.015 h1.52
  text "ANSI IPC-6012 TYPE 3 CLASS 2" at 288.258,101.015 h1.52
  text "OTHER +/-" at 288.258,97.289 h1.52
  text "DRILLING:" at 260.292,93.972 h1.52
  text "NC_DRILL FILES" at 305.022,91.3 h1.52
  text "REFERENCE:" at 262.191,91.2 h1.52
  text "X" at 278.885,91.197 h1.52
  text "AS SHOWN" at 283.406,91.2 h1.52
  text "X" at 301.771,91.2 h1.52
  text "OTHER" at 312.591,87.587 h1.52
  text "PTH COPPER THICKNESS:" at 262.183,87.497 h1.52
  text "X" at 291.12,87.497 h1.52
  text "20-30 um" at 294.371,87.497 h1.52
  text "BOARD FINISH:" at 260.292,83.748 h1.52
  text "SILKSCREEN:" at 264.235,80.951 h1.52
  text "X" at 288.563,80.951 h1.52
  text "TOP" at 291.534,80.951 h1.52
  text "BOTTOM" at 304.514,80.951 h1.52
  text "SILKSCREEN COLOR:" at 264.235,77.009 h1.52
  text "X" at 288.537,77.009 h1.52
  text "WHITE" at 291.534,77.009 h1.52
  text "OTHER" at 304.514,77.009 h1.52
  text "X" at 291.777,73.465 h1.52
  text "GREEN" at 294.862,73.365 h1.52
  text "OTHER" at 310.559,73.365 h1.52
  text "SOLDER RESIST COLOR:" at 264.235,73.191 h1.52
  text "X" at 291.865,69.447 h1.52
  text "MATTE" at 294.862,69.447 h1.52
  text "SEMI-GLOSS" at 310.547,69.431 h1.52
  text "IMMERSION GOLD (ENIG)" at 287.242,65.059 h1.52
  text "ENEPIG" at 321.215,64.876 h1.52
  text "SURFACE FINISH:" at 260.292,64.85 h1.52
  text "X" at 282.721,64.85 h1.52
  text "IMM. TIN/SILVER OR EQUIV" at 268.663,61.362 h1.52
  text "OTHER" at 305.022,61.262 h1.52
  text "ARRAY/PANEL:" at 260.292,57.316 h1.52
  text "CUT AND TRIM PER M1 BOARD OUTLINE" at 287.242,57.107 h1.52
  text "N.C. ROUTE" at 287.242,53.653 h1.52
  text "V. SCORE" at 309.238,53.653 h1.52
  text "X" at 304.595,53.613 h1.52
  text "CERTIFICATION:" at 260.292,50.374 h1.52
  text "MATERIALS AND WORKMANSHIP FOR ALL PCBS" at 278.707,50.374 h1.52
  text "TO MEET OR EXCEED THE REQUIREMENTS OF:" at 278.707,47.984 h1.52
  text "X" at 269.5,44.717 h1.52
  text "ANSI IPC-A-600F CLASS ->" at 272.751,44.717 h1.52
  text "X" at 314.61,44.717 h1.52
  text "2" at 317.404,44.717 h1.52
  text "1" at 309.403,44.679 h1.52
  text "3" at 326.396,44.679 h1.52
  text "X" at 290.125,40.966 h1.52
  text "RoHS" at 293.376,40.966 h1.52
  text "OTHER" at 309.744,40.966 h1.52
  text "PER ORDER" at 319.829,40.966 h1.52
  text "ALL BOARDS MUST MEET OR EXCEED UL94-V0 REQUIREMENTS." at 260.992,37.059 h1.52
  text "PCB MUST BEAR THE UL94V-0 UL REGISTERED MATERIAL ID NUMBER" at 260.992,34.111 h1.52
  text "ADDITIONAL REQUIREMENTS:" at 260.292,29.807 h1.52
  text "MICROSECTION:" at 262.191,27.086 h1.52
  text "YES" at 285.197,27.086 h1.52
  text "REQUIRED" at 307.079,23.42 h1.52
  text "BARE BOARD ELEC. TEST:" at 262.191,23.348 h1.52
  text "NONE" at 295.357,23.348 h1.52
  text "X" at 304.082,23.348 h1.52
  text "PER ORDER" at 322.116,23.348 h1.52
  text "XX MIL VIAS REQUIRE NON-CONDUCTIVE FILL AND PLANARIZE" at 266.462,18.142 h1.5
  text "XX MIL VIAS REQUIRE CONDUCTIVE FILL AND PLANARIZE" at 266.666,15.501 h1.52
  text "FAB NOTES:" at 108.55,13.892 h1.52
  text "OUTER XX MIL VIAS REQUIRE 50 OHM SINGLE-ENDED IMPEDANCE" at 266.641,11.351 h1.47
  text "1. THE SOLDER MASK IMAGES THAT ARE THE SAME SIZE AS THE COMPONENT PADS MAY BE ENLARGED AS PER THE" at 108.853,10.129 h1.52
  text "LAYER 2 & 3 (INNER LAYERS) XX MIL WIDE, XX MIL SPACE" at 266.644,7.416 h1.52
  text "MANUFACTURING CAPABILITIES BUT NOT BEYOND 0.08MM PER SIDE OR 0.15MM OVERALL." at 112.951,6.736 h1.52
  text "ALL OTHER SOLDER MASK IMAGES SHALL NOT BE MODIFIED." at 112.951,3.342 h1.52
  text ".Layer_Name" at -13.265,-39.092 h1.52
M11 Gerber Information:
  lines w0.254: -35.337,-40.913 132.303,-40.913 ; -35.337,-35.748 132.354,-35.748 ; -35.337,-30.583 -35.337,-46.077 66.39,-46.077 132.354,-46.077 132.354,-30.583 -35.325,-30.583 -35.325,-46.077 4.693,-46.077 ; 27.274,-46.077 27.274,-30.583 ; 59.456,-35.748 59.456,-30.583 ; 80.792,-35.748 80.792,-30.583 ; 96.59,-46.242 96.59,-41.09
  text "ALL ARTWORK VIEWED FROM TOP SIDE" at -33.724,-33.94 h1.52
  text "BOARD #:" at 29.179,-33.94 h1.52
  text ".PRJ_Number" at 43.034,-33.94 h1.52
  text "REV:" at 64.485,-33.94 h1.52
  text ".PCB_Rev" at 71.889,-33.94 h1.52
  text "SVN REV:" at 85.77,-33.94 h1.52
  text ".VersionControl_RevNumber" at 98.622,-33.94 h1.52
  text "LAYER NAME =" at -33.724,-39.092 h1.52
  text "TID #:" at 29.179,-39.105 h1.52
  text ".TID" at 43.034,-39.105 h1.52
  text "PLOT NAME =" at -33.724,-44.32 h1.52
  text ".plot_File_Name" at -13.265,-44.32 h1.52
  text "GENERATED    :" at 29.23,-44.32 h1.52
  text ".Print_Date" at 51.315,-44.32 h1.52
  text ".Print_Time" at 69.831,-44.32 h1.52
  text "TEXAS INSTRUMENTS" at 101.95,-44.32 h1.52
M12 Stackup:
  drawing of 292 lines, arcs and shapes, not listed
  text "STACKUP TABLE:" at 105.617,105.359 h2.03
  text "Layer" at 107.304,101 h1.52
  text "Name" at 117.716,101 h1.52
  text "Material" at 139.554,101 h1.52
  text "Thickness" at 161.392,101 h1.52
  text "Constant" at 177.898,101 h1.52
  text "Board Layer Stack" at 192.372,101 h1.52
  text "Board Layer Stack" at 220.812,101 h1.52
  text "1" at 107.304,97.952 h1.52
  text "Top Overlay" at 117.716,97.952 h1.52
  text "2" at 107.304,94.904 h1.52
  text "Top Solder" at 117.716,94.904 h1.52
  text "Solder Resist" at 139.554,94.904 h1.52
  text "0.40mil" at 161.392,94.904 h1.52
  text "3.5" at 177.898,94.904 h1.52
  text "3" at 107.304,91.856 h1.52
  text "Top Layer" at 117.716,91.856 h1.52
  text "Copper" at 139.554,91.856 h1.52
  text "2.10mil" at 161.392,91.856 h1.52
  text "4" at 107.304,88.808 h1.52
  text "Dielectric1" at 117.716,88.808 h1.52
  text "FR-4 High Tg" at 139.554,88.808 h1.52
  text "57.00mil" at 161.392,88.808 h1.52
  text "4.8" at 177.898,88.808 h1.52
  text "5" at 107.304,85.76 h1.52
  text "Bottom Layer" at 117.716,85.76 h1.52
  text "Copper" at 139.554,85.76 h1.52
  text "2.10mil" at 161.392,85.76 h1.52
  text "6" at 107.304,82.712 h1.52
  text "Bottom Solder" at 117.716,82.712 h1.52
  text "Solder Resist" at 139.554,82.712 h1.52
  text "0.40mil" at 161.392,82.712 h1.52
  text "3.5" at 177.898,82.712 h1.52
  text ".Layer_Name" at -13.265,-39.092 h1.52
M13 Component Bodies Top:
  text ".Layer_Name" at -13.265,-39.092 h1.52
M14 Component Bodies Bottom:
  text ".Layer_Name" at -13.265,-39.092 h1.52
M15 Courtyards Top:
  text ".Layer_Name" at -13.265,-39.092 h1.52
M16 Courtyards Bottom:
  text ".Layer_Name" at -13.265,-39.092 h1.52
Drill Drawing:
  circle w0.254: c108.141,67.181 r0.847
  lines w0.254: 107.294,51.095 108.988,51.095 108.988,52.788 107.294,52.788 107.294,51.095
  lines w0.381: 105.776,46.142 238.075,46.142 ; 105.776,72.812 238.075,72.812 ; 119.768,42.332 119.768,76.622 ; 133.48,42.332 133.48,76.622 ; 162.682,42.332 162.682,76.622 ; 175.531,42.332 175.531,76.622 ; 194.17,42.332 194.17,76.622 ; 222.254,42.332 222.254,76.622 ; 105.776,42.332 238.075,42.332 238.075,76.622 105.776,76.622 105.776,42.332
  text "Symbol" at 108.062,73.955 h1.83
  text "Count" at 120.911,73.955 h1.83
  text "Hole Size" at 134.623,73.955 h1.83
  text "Plated" at 163.825,73.955 h1.83
  text "Hole Type" at 176.674,73.955 h1.83
  text "Tolerance(Mils)" at 195.313,73.955 h1.83
  text "Tenting" at 223.397,73.955 h1.83
  text "DRILL TABLE:" at 105.795,71.383 h2.03
  text "24" at 120.911,70.145 h1.52
  text "12.00mil (0.305mm)" at 134.623,70.145 h1.52
  text "PTH" at 163.825,70.145 h1.52
  text "Round" at 176.674,70.145 h1.52
  text "+0/-12" at 195.313,70.145 h1.52
  text "Both" at 223.397,70.145 h1.52
  text "A" at 107.323,69.891 h1.69
  text "8" at 120.911,66.335 h1.52
  text "35.43mil (0.900mm)" at 134.623,66.335 h1.52
  text "PTH" at 163.825,66.335 h1.52
  text "Round" at 176.674,66.335 h1.52
  text "5" at 120.911,62.525 h1.52
  text "214.57mil (5.450mm)" at 134.623,62.525 h1.52
  text "PTH" at 163.825,62.525 h1.52
  text "Round" at 176.674,62.525 h1.52
  text "+/-3" at 195.313,62.525 h1.52
  text "E" at 107.323,62.271 h1.69
  text "4" at 120.911,58.715 h1.52
  text "63.00mil (1.600mm)" at 134.623,58.715 h1.52
  text "PTH" at 163.825,58.715 h1.52
  text "Round" at 176.674,58.715 h1.52
  text "+/-3" at 195.313,58.715 h1.52
  text "B" at 107.323,58.461 h1.69
  text "4" at 120.911,54.905 h1.52
  text "125.98mil (3.200mm)" at 134.623,54.905 h1.52
  text "PTH" at 163.825,54.905 h1.52
  text "Round" at 176.674,54.905 h1.52
  text "+/-3" at 195.313,54.905 h1.52
  text "D" at 107.323,54.651 h1.69
  text "2" at 120.911,51.095 h1.52
  text "40.00mil (1.016mm)" at 134.623,51.095 h1.52
  text "PTH" at 163.825,51.095 h1.52
  text "Round" at 176.674,51.095 h1.52
  text "2" at 120.911,47.285 h1.52
  text "64.96mil (1.650mm)" at 134.623,47.285 h1.52
  text "PTH" at 163.825,47.285 h1.52
  text "Round" at 176.674,47.285 h1.52
  text "+/-3" at 195.313,47.285 h1.52
  text "C" at 107.323,47.031 h1.69
  text "49 Total" at 120.911,43.475 h1.52
  text ".Layer_Name" at -13.265,-39.092 h1.52
M17 Embedded Cavity:
  text ".Layer_Name" at -13.265,-39.092 h1.52
M18 Embedded Assembly:
  text ".Layer_Name" at -13.265,-39.092 h1.52
M19 Embedded Keepout:
  text ".Layer_Name" at -13.265,-39.092 h1.52

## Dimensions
0,0 to -4.445,-4.445 on M2 Board Dimensions
0,0 to -4.445,-4.445 on M2 Board Dimensions
0,0 to -4.445,48.895 on M2 Board Dimensions
0,0 to 74.93,-4.445 on M2 Board Dimensions
-27.92,-27.446 to -2.52,-27.446 on M2 Board Dimensions
-0.721,-0.767 to -7.949,-6.356 on M2 Board Dimensions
